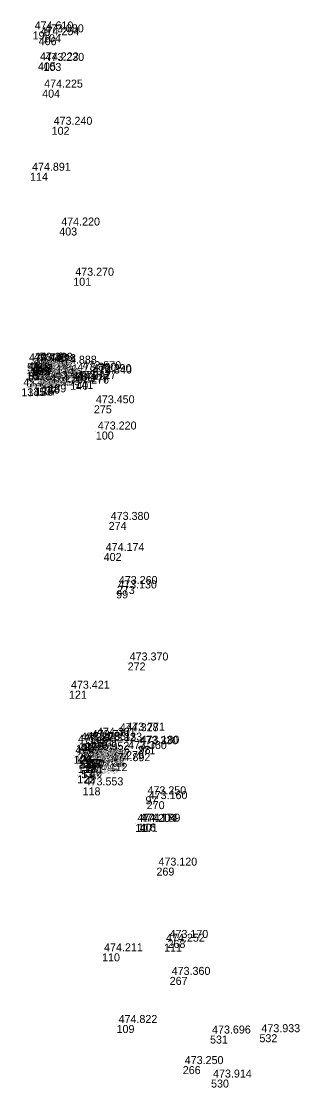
# Model space of a CAD drawing. Extents: x -874038 to -859694, y -1059487 to -1049069.
# Drawn here: x -866308.9 to -866267.1, y -1053460.5 to -1053300.6 of the extents above; entities that cross this region are included whole.
import ezdxf

# ---------------------------------------------------------------- set-up
doc = ezdxf.new("R2010")
doc.units = 0
doc.layers.add('Vrstva 60', color=7, linetype='Continuous')
doc.layers.add('Vrstva 61', color=7, linetype='Continuous')

msp = doc.modelspace()

# ---------------------------------------------------------------- linework, layer by layer
at = {"layer": 'Vrstva 60'}
for p, q in [((-866307.16, -1053302.13), (-866307.16, -1053302.13)), ((-866305.6, -1053302.56), (-866305.6, -1053302.56)), ((-866306.26, -1053302.99), (-866306.26, -1053302.99)), ((-866306.36, -1053306.77), (-866306.36, -1053306.77)), ((-866305.54, -1053306.85), (-866305.54, -1053306.85)), ((-866305.73, -1053310.85), (-866305.73, -1053310.85)), ((-866304.31, -1053316.42), (-866304.31, -1053316.42)), ((-866307.55, -1053323.31), (-866307.55, -1053323.31)), ((-866303.17, -1053331.52), (-866303.17, -1053331.52)), ((-866301.07, -1053339.05), (-866301.07, -1053339.05)), ((-866308, -1053351.89), (-866308, -1053351.89)), ((-866308, -1053351.89), (-866308, -1053351.89)), ((-866307.27, -1053351.8), (-866307.27, -1053351.8)), ((-866307.05, -1053352.09), (-866307.05, -1053352.09)), ((-866306.85, -1053351.75), (-866306.85, -1053351.75)), ((-866306.85, -1053351.75), (-866306.85, -1053351.75)), ((-866306.77, -1053351.99), (-866306.77, -1053351.99)), ((-866303.66, -1053352.23), (-866303.66, -1053352.23)), ((-866308.12, -1053353.2), (-866308.12, -1053353.2)), ((-866307.85, -1053353.22), (-866307.85, -1053353.22)), ((-866307.85, -1053353.22), (-866307.85, -1053353.22)), ((-866307.34, -1053352.47), (-866307.34, -1053352.47)), ((-866307.25, -1053352.48), (-866307.25, -1053352.48)), ((-866307.09, -1053353.11), (-866307.09, -1053353.11)), ((-866306.68, -1053353.05), (-866306.68, -1053353.05)), ((-866306.68, -1053353.05), (-866306.68, -1053353.05)), ((-866306.45, -1053353.54), (-866306.45, -1053353.54)), ((-866300.73, -1053353.3), (-866300.73, -1053353.3)), ((-866299.99, -1053353.06), (-866299.99, -1053353.06)), ((-866298.44, -1053353.5), (-866298.44, -1053353.5)), ((-866298.39, -1053353.71), (-866298.39, -1053353.71)), ((-866307.97, -1053354.3), (-866307.97, -1053354.3)), ((-866307.11, -1053354.25), (-866307.11, -1053354.25)), ((-866306.41, -1053354.1), (-866306.41, -1053354.1)), ((-866305.92, -1053354.35), (-866305.92, -1053354.35)), ((-866305.75, -1053355.21), (-866305.75, -1053355.21)), ((-866304.8, -1053355.02), (-866304.8, -1053355.02)), ((-866301.52, -1053354.65), (-866301.52, -1053354.65)), ((-866300.74, -1053354.51), (-866300.74, -1053354.51)), ((-866308.85, -1053355.61), (-866308.85, -1053355.61)), ((-866307.93, -1053355.57), (-866307.93, -1053355.57)), ((-866306.76, -1053355.52), (-866306.76, -1053355.52)), ((-866306.22, -1053355.46), (-866306.22, -1053355.46)), ((-866297.98, -1053358.17), (-866297.98, -1053358.17)), ((-866297.69, -1053362.1), (-866297.69, -1053362.1)), ((-866295.76, -1053375.65), (-866295.76, -1053375.65)), ((-866296.51, -1053380.31), (-866296.51, -1053380.31)), ((-866294.54, -1053385.26), (-866294.54, -1053385.26)), ((-866294.64, -1053385.92), (-866294.64, -1053385.92)), ((-866292.92, -1053396.72), (-866292.92, -1053396.72)), ((-866301.71, -1053400.95), (-866301.71, -1053400.95)), ((-866297.82, -1053408.01), (-866297.82, -1053408.01)), ((-866294.39, -1053407.33), (-866294.39, -1053407.33)), ((-866293.43, -1053407.23), (-866293.43, -1053407.23)), ((-866300.65, -1053409.06), (-866300.65, -1053409.06)), ((-866300.21, -1053408.72), (-866300.21, -1053408.72)), ((-866299.78, -1053408.83), (-866299.78, -1053408.83)), ((-866299.26, -1053408.64), (-866299.26, -1053408.64)), ((-866298.61, -1053408.35), (-866298.61, -1053408.35)), ((-866291.45, -1053409.28), (-866291.45, -1053409.28)), ((-866291.28, -1053409.19), (-866291.28, -1053409.19)), ((-866301.04, -1053410.71), (-866301.04, -1053410.71)), ((-866300.84, -1053410.7), (-866300.84, -1053410.7)), ((-866300.84, -1053410.7), (-866300.84, -1053410.7)), ((-866300.4, -1053410.34), (-866300.4, -1053410.34)), ((-866299.55, -1053411.3), (-866299.55, -1053411.3)), ((-866299.22, -1053411.24), (-866299.22, -1053411.24)), ((-866299.12, -1053411.24), (-866299.12, -1053411.24)), ((-866298.78, -1053410.12), (-866298.78, -1053410.12)), ((-866298.74, -1053411.17), (-866298.74, -1053411.17)), ((-866298.74, -1053411.17), (-866298.74, -1053411.17)), ((-866298.7, -1053410.66), (-866298.7, -1053410.66)), ((-866293.16, -1053410), (-866293.16, -1053410)), ((-866300.39, -1053412.07), (-866300.39, -1053412.07)), ((-866300.25, -1053411.43), (-866300.25, -1053411.43)), ((-866300.08, -1053411.39), (-866300.08, -1053411.39)), ((-866300.08, -1053411.39), (-866300.08, -1053411.39)), ((-866299.87, -1053412.86), (-866299.87, -1053412.86)), ((-866299.87, -1053412.86), (-866299.87, -1053412.86)), ((-866299.32, -1053412.07), (-866299.32, -1053412.07)), ((-866299.28, -1053412.04), (-866299.28, -1053412.04)), ((-866298.95, -1053411.55), (-866298.95, -1053411.55)), ((-866298.55, -1053412.71), (-866298.55, -1053412.71)), ((-866298.55, -1053412.71), (-866298.55, -1053412.71)), ((-866295.62, -1053411.81), (-866295.62, -1053411.81)), ((-866300.46, -1053413.63), (-866300.46, -1053413.63)), ((-866300.46, -1053413.66), (-866300.46, -1053413.66)), ((-866299.67, -1053415.44), (-866299.67, -1053415.44)), ((-866290.25, -1053416.78), (-866290.25, -1053416.78)), ((-866290.06, -1053417.5), (-866290.06, -1053417.5)), ((-866291.77, -1053420.92), (-866291.77, -1053420.92)), ((-866291.38, -1053420.86), (-866291.38, -1053420.86)), ((-866291.12, -1053420.89), (-866291.12, -1053420.89)), ((-866288.6, -1053427.47), (-866288.6, -1053427.47)), ((-866286.94, -1053438.31), (-866286.94, -1053438.31)), ((-866287.46, -1053438.87), (-866287.46, -1053438.87)), ((-866296.75, -1053440.32), (-866296.75, -1053440.32)), ((-866286.62, -1053443.85), (-866286.62, -1053443.85)), ((-866294.58, -1053451.06), (-866294.58, -1053451.06)), ((-866280.57, -1053452.64), (-866280.57, -1053452.64)), ((-866273.17, -1053452.44), (-866273.17, -1053452.44)), ((-866284.66, -1053457.22), (-866284.66, -1053457.22)), ((-866280.42, -1053459.24), (-866280.42, -1053459.24))]:
    msp.add_line(p, q, dxfattribs=at)

# ---------------------------------------------------------------- texts
for s, p in [('193', (-866307.16, -1053303.33)), ('104', (-866305.6, -1053303.76)), ('406', (-866306.26, -1053304.19)), ('405', (-866306.36, -1053307.97)), ('103', (-866305.54, -1053308.05)), ('404', (-866305.73, -1053312.05)), ('102', (-866304.31, -1053317.62)), ('114', (-866307.55, -1053324.51)), ('403', (-866303.17, -1053332.72)), ('101', (-866301.07, -1053340.25)), ('56', (-866308, -1053353.09)), ('9', (-866308, -1053353.09)), ('313', (-866307.27, -1053353)), ('758', (-866307.05, -1053353.29)), ('50', (-866306.85, -1053352.95)), ('6', (-866306.85, -1053352.95)), ('142', (-866306.77, -1053353.19)), ('113', (-866303.66, -1053353.43)), ('14', (-866308.12, -1053354.4)), ('8', (-866307.85, -1053354.42)), ('55', (-866307.85, -1053354.42)), ('10', (-866307.34, -1053353.67)), ('285', (-866307.25, -1053353.68)), ('312', (-866307.09, -1053354.31)), ('51', (-866306.68, -1053354.25)), ('7', (-866306.68, -1053354.25)), ('11', (-866306.45, -1053354.74)), ('282', (-866300.73, -1053354.5)), ('278', (-866299.99, -1053354.26)), ('277', (-866298.44, -1053354.7)), ('276', (-866298.39, -1053354.91)), ('13', (-866307.97, -1053355.5)), ('284', (-866307.11, -1053355.45)), ('12', (-866306.41, -1053355.3)), ('283', (-866305.92, -1053355.55)), ('138', (-866305.75, -1053356.41)), ('139', (-866304.8, -1053356.22)), ('140', (-866301.52, -1053355.84)), ('141', (-866300.74, -1053355.71)), ('134', (-866308.85, -1053356.81)), ('135', (-866307.93, -1053356.77)), ('136', (-866306.76, -1053356.72)), ('137', (-866306.22, -1053356.66)), ('275', (-866297.98, -1053359.37)), ('100', (-866297.69, -1053363.3)), ('274', (-866295.76, -1053376.85)), ('402', (-866296.51, -1053381.51)), ('273', (-866294.54, -1053386.46)), ('99', (-866294.64, -1053387.12)), ('272', (-866292.92, -1053397.92)), ('121', (-866301.71, -1053402.15)), ('131', (-866297.82, -1053409.21)), ('132', (-866294.39, -1053408.53)), ('133', (-866293.43, -1053408.43)), ('120', (-866300.65, -1053410.26)), ('127', (-866300.21, -1053409.92)), ('128', (-866299.78, -1053410.03)), ('129', (-866299.26, -1053409.84)), ('130', (-866298.61, -1053409.55)), ('271', (-866291.45, -1053410.48)), ('98', (-866291.28, -1053410.39)), ('126', (-866301.04, -1053411.91)), ('124', (-866300.84, -1053411.9)), ('125', (-866300.84, -1053411.9)), ('22', (-866300.4, -1053411.54)), ('18', (-866300.08, -1053412.59)), ('315', (-866299.55, -1053412.5)), ('314', (-866299.22, -1053412.44)), ('280', (-866299.12, -1053412.44)), ('21', (-866298.78, -1053411.32)), ('46', (-866298.74, -1053412.37)), ('20', (-866298.7, -1053411.86)), ('15', (-866298.74, -1053412.37)), ('279', (-866293.16, -1053411.2)), ('119', (-866300.39, -1053413.27)), ('23', (-866300.25, -1053412.63)), ('54', (-866300.08, -1053412.59)), ('53', (-866299.87, -1053414.06)), ('17', (-866299.87, -1053414.06)), ('281', (-866299.28, -1053413.24)), ('19', (-866299.32, -1053413.27)), ('757', (-866298.95, -1053412.76)), ('47', (-866298.55, -1053413.91)), ('16', (-866298.55, -1053413.91)), ('112', (-866295.62, -1053413.01)), ('122', (-866300.46, -1053414.86)), ('123', (-866300.46, -1053414.83)), ('118', (-866299.67, -1053416.64)), ('97', (-866290.25, -1053417.98)), ('270', (-866290.06, -1053418.7)), ('117', (-866291.77, -1053422.12)), ('116', (-866291.38, -1053422.06)), ('401', (-866291.12, -1053422.09)), ('269', (-866288.6, -1053428.67)), ('268', (-866286.94, -1053439.51)), ('111', (-866287.46, -1053440.07)), ('110', (-866296.75, -1053441.52)), ('267', (-866286.62, -1053445.05)), ('109', (-866294.58, -1053452.26)), ('531', (-866280.57, -1053453.84)), ('532', (-866273.17, -1053453.64)), ('266', (-866284.66, -1053458.42)), ('530', (-866280.42, -1053460.44))]:
    msp.add_text(s, height=1.2, dxfattribs=at).set_placement(p)
at = {"layer": 'Vrstva 61'}
for s, p in [('474.610', (-866306.86, -1053301.83)), ('473.080', (-866305.3, -1053302.26)), ('474.254', (-866305.96, -1053302.69)), ('474.222', (-866306.06, -1053306.47)), ('473.230', (-866305.24, -1053306.55)), ('474.225', (-866305.43, -1053310.55)), ('473.240', (-866304.01, -1053316.12)), ('474.891', (-866307.25, -1053323.01)), ('474.220', (-866302.87, -1053331.22)), ('473.270', (-866300.77, -1053338.75)), ('474.493', (-866307.7, -1053351.59)), ('473.743', (-866307.7, -1053351.59)), ('473.388', (-866306.97, -1053351.5)), ('474.974', (-866306.75, -1053351.79)), ('474.493', (-866306.55, -1053351.45)), ('474.193', (-866306.55, -1053351.45)), ('474.498', (-866306.47, -1053351.69)), ('475.977', (-866307.83, -1053352.9)), ('474.488', (-866307.55, -1053352.92)), ('473.738', (-866307.55, -1053352.92)), ('474.500', (-866307.04, -1053352.17)), ('474.440', (-866306.95, -1053352.18)), ('473.381', (-866306.79, -1053352.81)), ('474.499', (-866306.38, -1053352.75)), ('474.199', (-866306.38, -1053352.75)), ('475.981', (-866306.15, -1053353.24)), ('474.888', (-866303.35, -1053351.93)), ('473.300', (-866300.43, -1053353)), ('473.570', (-866299.69, -1053352.76)), ('473.290', (-866298.14, -1053353.2)), ('473.340', (-866298.09, -1053353.41)), ('475.982', (-866307.67, -1053354)), ('472.910', (-866306.81, -1053353.95)), ('475.983', (-866306.11, -1053353.8)), ('473.320', (-866305.62, -1053354.05)), ('473.748', (-866305.45, -1053354.91)), ('474.282', (-866304.5, -1053354.72)), ('474.297', (-866301.22, -1053354.34)), ('473.727', (-866300.44, -1053354.21)), ('472.759', (-866308.55, -1053355.31)), ('473.248', (-866307.63, -1053355.27)), ('473.367', (-866306.46, -1053355.22)), ('473.726', (-866305.92, -1053355.16)), ('473.450', (-866297.68, -1053357.87)), ('473.220', (-866297.39, -1053361.8)), ('473.380', (-866295.46, -1053375.35)), ('474.174', (-866296.21, -1053380.01)), ('473.260', (-866294.24, -1053384.96)), ('473.130', (-866294.34, -1053385.62)), ('473.370', (-866292.62, -1053396.42)), ('473.421', (-866301.41, -1053400.65)), ('474.301', (-866297.52, -1053407.71)), ('474.328', (-866294.09, -1053407.03)), ('473.771', (-866293.13, -1053406.93)), ('473.475', (-866300.35, -1053408.76)), ('473.323', (-866299.91, -1053408.42)), ('473.352', (-866299.48, -1053408.53)), ('473.753', (-866298.96, -1053408.34)), ('473.771', (-866298.31, -1053408.05)), ('473.330', (-866291.15, -1053408.98)), ('473.180', (-866290.98, -1053408.89)), ('474.012', (-866300.74, -1053410.41)), ('473.293', (-866300.54, -1053410.4)), ('474.000', (-866300.54, -1053410.4)), ('475.981', (-866300.09, -1053410.04)), ('473.676', (-866298.93, -1053410.94)), ('473.290', (-866298.82, -1053410.94)), ('475.952', (-866298.48, -1053409.82)), ('474.446', (-866298.44, -1053410.87)), ('474.196', (-866298.44, -1053410.87)), ('475.936', (-866298.4, -1053410.36)), ('473.360', (-866292.86, -1053409.7)), ('473.497', (-866300.09, -1053411.77)), ('475.969', (-866299.95, -1053411.13)), ('474.446', (-866299.78, -1053411.09)), ('473.746', (-866299.78, -1053411.09)), ('474.450', (-866299.57, -1053412.56)), ('473.750', (-866299.57, -1053412.56)), ('473.429', (-866299.25, -1053411)), ('474.456', (-866299.02, -1053411.77)), ('474.390', (-866298.98, -1053411.74)), ('474.971', (-866298.65, -1053411.26)), ('474.461', (-866298.24, -1053412.41)), ('474.211', (-866298.24, -1053412.41)), ('474.892', (-866295.32, -1053411.51)), ('473.399', (-866300.16, -1053413.36)), ('474.058', (-866300.16, -1053413.33)), ('473.553', (-866299.37, -1053415.14)), ('473.250', (-866289.95, -1053416.48)), ('473.160', (-866289.76, -1053417.2)), ('474.171', (-866291.08, -1053420.56)), ('474.189', (-866290.82, -1053420.59)), ('474.204', (-866291.47, -1053420.62)), ('473.120', (-866288.3, -1053427.17)), ('473.170', (-866286.64, -1053438.01)), ('474.252', (-866287.16, -1053438.57)), ('474.211', (-866296.45, -1053440.02)), ('473.360', (-866286.32, -1053443.55)), ('474.822', (-866294.28, -1053450.76)), ('473.696', (-866280.27, -1053452.34)), ('473.933', (-866272.87, -1053452.14)), ('473.250', (-866284.36, -1053456.92)), ('473.914', (-866280.12, -1053458.94))]:
    msp.add_text(s, height=1.2, dxfattribs=at).set_placement(p)

doc.saveas('drawing.dxf')
